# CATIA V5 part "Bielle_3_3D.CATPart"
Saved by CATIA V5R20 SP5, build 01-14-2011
Part number: Bielle_3_3D
Bounding box of the stored display mesh (mm): x 0 to 155, y 248.444 to 667.318, z -122.026 to 180.124
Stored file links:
  J:\Thinkmotion\Projet IAO\A envoyer\Bielle_3_3D.CATPart
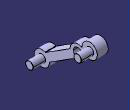
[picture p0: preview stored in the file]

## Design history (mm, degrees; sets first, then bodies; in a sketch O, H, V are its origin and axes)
Body1 (main body)
  Line1 to Line5: stored without definition
  Sketch1 on yz-plane, origin (0, 0, 0), H (0, 1, 0), V (0, 0, 1)
    line L1 (321.5985, -27.7533) -> (487.6569, 77.528)
    point P2 (487.6569, 77.528)
    line L2 (348.3712, -69.9815) -> (514.4296, 35.2998)
    point P3 (348.3712, -69.9815)
    line L3 (560.7982, 123.8997) -> (567.3901, 128.079)
    point P5 (560.7982, 123.8997)
    line L4 (587.571, 81.6715) -> (594.1628, 85.8508)
    point P7 (587.571, 81.6715)
    point P8 (594.1628, 85.8508)
    arc A1 centre (537.6139, 79.5998) radius 50 from (514.4296, 35.2998) to (587.571, 81.6715) ccw
    point P9 (537.6139, 79.5998)
    point P10 (587.571, 81.6715)
    arc A2 centre (537.6139, 79.5998) radius 50 from (560.7982, 123.8997) to (487.6569, 77.528) ccw
    point P11 (560.7982, 123.8997)
    point P12 (487.6569, 77.528)
    circle A3 centre (537.6139, 79.5998) radius 30
    arc A4 centre (298.4142, -72.0532) radius 50 from (321.5985, -27.7533) to (348.3712, -69.9815) ccw
    point P13 (298.4142, -72.0532)
    point P14 (348.3712, -69.9815)
    arc A5 centre (617.3472, 130.1508) radius 50 from (594.1628, 85.8508) to (567.3901, 128.079) ccw
    point P15 (617.3472, 130.1508)
    point P16 (594.1628, 85.8508)
    reference projected point E1 (298.4142, -72.0532) from Line1
    reference projected point E2 (617.3472, 130.1508) from Line2
    reference projected line E3 (298.4142, -72.0532) -> (617.3472, 130.1508) from Line3
    reference projected line E4 (298.4142, -72.0532) -> (617.3472, 130.1508) from Line4
    reference projected point E5 (537.6139, 79.5998) from Line5
    radius A1 = 50
    radius A2 = 50
    radius A3 = 30
    radius A4 = 50
    radius A5 = 50
    distance L1 E4 = 25
    distance L1 L2 = 50
    coincidence: P5 L1, P7 L2, P8 L2, P10 L4, P7 P10, A2 P2, P11 L3, P11 P5, P12 P2, P14 L2, P14 P3, P16 L4, P16 P8, E1 P13, P15 E2, P9 E5
    parallelism: L3 L1, L1 E3
  Pad1: profile Sketch1, direction (1, 0, 0), length 72
  Line6: stored without definition
  Line7: stored without definition
  Sketch2 on end face of Pad1, origin (72, 0, 0), H (0, 1, 0), V (0, 0, 1)
    circle A1 centre (618.933, 128.204) radius 25
    circle A2 centre (298.4142, -72.0532) radius 25
    point P2 (298.4142, -72.0532)
    reference projected point E1 (618.933, 128.204) from Line6
    reference projected point E2 (298.4142, -72.0532) from Line7
    radius A2 = 25
    radius A1 = 25
    concentricity: A1 E1
    coincidence: P2 E2
  Pad2: profile Sketch2, direction (1, 0, 0), length 83
  Fillet1: radius 5, on edge [face of Pad1 from Sketch1.A4 | face of Pad1 from Sketch1.L1]; edge [face of Pad1 from Sketch1.L1 | face of Pad1 from Sketch1.A2]; edge [face of Pad1 from Sketch1.A2 | face of Pad1 from Sketch1.L3]; edge [face of Pad1 from Sketch1.L3 | face of Pad1 from Sketch1.A5]; edge [face of Pad1 from Sketch1.A5 | face of Pad1 from Sketch1.L4]; edge [face of Pad1 from Sketch1.L4 | face of Pad1 from Sketch1.A1]; edge [face of Pad1 from Sketch1.A1 | face of Pad1 from Sketch1.L2]; edge [face of Pad1 from Sketch1.L2 | face of Pad1 from Sketch1.A4]
  Chamfer1: length 1, angle 45, on edge [face of Pad2 from Sketch2.A2 | end face of Pad2]; edge [face of Pad2 from Sketch2.A1 | end face of Pad2]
